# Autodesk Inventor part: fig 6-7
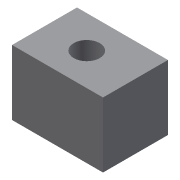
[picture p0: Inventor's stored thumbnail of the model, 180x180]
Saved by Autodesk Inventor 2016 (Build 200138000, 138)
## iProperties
Created: 2009-09
Part Number: fig 6-7
Document SubType Name: Modeling
Designer: Sham
Density: 1 g/cm^3
Material: Generic
Appearance: Default
Author: Sham
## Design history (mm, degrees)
sketch "Sketch1"
  geometry: L1 (-28, 20)-(0, 20); L2 (0, 20)-(0, 0); L3 (0, 0)-(-28, 0); L4 (-28, 0)-(-28, 20)
  constraints: 8 end point, 2 parallel, 1 horizontal, 1 perpendicular
extrude "Extrusion1" new body sketch "Sketch1" distance "d0" = 20; taper "d1" = 0 deg
hole "Hole1" diameter "d4" = 8; stored, may be unused: countersink angle "d8" = 90 deg, drill point angle "d10" = 118 deg; dims "d2" = 10, "d3" = 15, "d5" = 6, "d6" = 4, "d7" = 2, "d9" = 15
body "Solid1"
